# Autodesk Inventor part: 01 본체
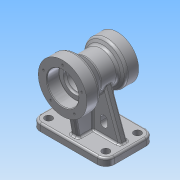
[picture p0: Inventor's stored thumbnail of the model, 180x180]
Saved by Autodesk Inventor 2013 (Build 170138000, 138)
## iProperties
Created: 2015-08
Part Number: 01 본체
Material: 알루미늄 6061
Document SubType Name: Modeling
Designer: Administrator
Density: 2.71 g/cm^3
Mass: 1062.79 g
Surface Area: 749.652 cm^2
Volume: 392.172 cm^3
Author: Administrator
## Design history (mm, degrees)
sketch "스케치1"
  geometry: L1 (-61, 40)-(61, 40); L2 (61, 40)-(61, -40); L3 (61, -40)-(-61, -40); L4 (-61, -40)-(-61, 40); L5 (-61, 40)-(61, -40); 2 further points
  constraints: 10 end point, 2 parallel, 1 coincident, 1 horizontal, 1 midpoint, 1 perpendicular
  dimensions: "d0" = 122 distance of L1.start L1.end; "d3" = 80 distance of L1.end L2.end
extrude "돌출1" new body sketch "스케치1" distance "d4" = 12; taper "d5" = 0 deg
sketch "스케치2"
  geometry: L1 (-40, 0)-(40, 0) reference; L2 (40, 0)-(40, 12) reference; L3 (-40, 12)-(40, 12) reference; L4 (-40, 0)-(-40, 12) reference; L5 (40, 0)-(40, 125); L6 (40, 125)-(20, 125); L7 (20, 125)-(14.804, 116); L8 (14.804, 116)-(-13.315, 116); L9 (-13.315, 116)-(-30, 130); L10 (-30, 130)-(-50, 130); L11 (-50, 130)-(-50, 90); L12 (-50, 90)-(40, 90); 1 further point
  constraints: 16 end point, 4 parallel, 2 perpendicular, 1 point on line
  dimensions: "d8" = 60 deg angle of L8 L7; "d9" = 40 deg angle of L8 L9; "d10" = 70 diameter of L6 L12; "d12" = 80 diameter of L10 L12; "d13" = 180 diameter of L1 L12; "d14" = 52 diameter of L8 L12; "d15" = 90 distance of L11.end L12.end; "d16" = 20 distance of L9.end L10.end; "d17" = 20 distance of L5.end L6.end
revolve "회전1" sketch "스케치2" stored, may be unused: angle "d18" = 90 deg
sketch "스케치3"
  geometry: L1 (61, 0)-(-61, 0) reference; L2 (-61, 0)-(-61, 12) reference; L3 (61, 12)-(-61, 12) reference; L4 (61, 0)-(61, 12) reference; L5 (25.091, 83.185)-(51, 12); L6 (25.091, 83.185)-(-25.091, 83.185); L7 (-25.091, 83.185)-(-51, 12); L8 (0, 0)-(0, 83.185); A1 r 26 centre (0, 90) between (25.091, 83.185) and (-25.091, 83.185) reference
  constraints: 8 end point, 2 point on circle, 2 point on line, 1 midpoint, 1 perpendicular, 1 other
  dimensions: "d19" = 70 deg angle of L3 L5; "d20" = 10 distance from line of L4 L5.end
extrude "돌출2" join sketch "스케치3" stored distance "d21" = 12; taper "d22" = 0 deg
extrude "돌출3" join sketch "스케치4" stored distance "d28" = 12; taper "d29" = 0 deg
sketch "스케치5"
  geometry: L1 (-47, 26)-(47, 26); L2 (47, 26)-(47, -26); L3 (47, -26)-(-47, -26); L4 (-47, -26)-(-47, 26); L5 (-47, 26)-(47, -26); 6 further points
  constraints: 10 end point, 5 coincident, 2 parallel, 1 horizontal, 1 midpoint, 1 perpendicular
  dimensions: "d30" = 94 distance of L1.start L1.end; "d32" = 52 distance of L1.end L2.end
hole "구멍1" sketch "스케치5" at (-47, 26), (-47, -26), (47, -26), (47, 26) diameter "d33" = 12; stored, may be unused: countersink angle "d37" = 90 deg, drill point angle "d39" = 118 deg; dims "d34" = 6, "d35" = 4, "d36" = 2, "d38" = 8
fillet "모깎기1" dims "d40" = 14
sketch "스케치6" dims "d41" = 66
  geometry: L1 (0, 0)-(0, 33); C1 r 40 at (0, 0) reference; 2 further points
  constraints: 2 coincident, 2 end point, 1 vertical, 1 vertical alignment, 2 other
hole "구멍2" sketch "스케치6" at (0, 33) diameter "d42" = 3.242; stored, may be unused: countersink angle "d46" = 90 deg, drill point angle "d48" = 118 deg; dims "d43" = 10, "d44" = 4, "d45" = 2, "d47" = 13
sketch "스케치7" dims "d52" = 54
  geometry: L1 (0, 0)-(0, -27); C1 r 35 at (0, 0) reference; 2 further points
  constraints: 2 coincident, 2 end point, 1 vertical, 1 vertical alignment, 2 other
hole "구멍3" sketch "스케치7" at (0, -27) diameter "d53" = 3.242; stored, may be unused: countersink angle "d57" = 90 deg, drill point angle "d59" = 118 deg; dims "d54" = 10, "d55" = 4, "d56" = 2, "d58" = 13
sketch "스케치8"
  geometry: C1 r 40 at (0, 0) reference; C2 r 26 at (0, 0); 1 further point
  constraints: 1 centre point, 1 coincident
  dimensions: "d63" = 52 diameter of C2
extrude "돌출4" cut sketch "스케치8" distance "d64" = 20; taper "d65" = 0 deg
sketch "스케치9"
  geometry: C1 r 26 at (0, 0) reference; C2 r 19 at (0, 0); 1 further point
  constraints: 1 centre point, 1 coincident
  dimensions: "d66" = 38 diameter of C2
extrude "돌출5" cut sketch "스케치9" distance "d67" = 3; taper "d68" = 0 deg
sketch "스케치10"
  geometry: C1 r 19 at (0, 0) reference; C2 r 16 at (0, 0); 1 further point
  constraints: 1 centre point, 1 coincident
  dimensions: "d69" = 32 diameter of C2
extrude "돌출6" cut sketch "스케치10" stored distance "d70" = 3; taper "d71" = 0 deg
sketch "스케치11"
  geometry: C1 r 16 at (0, 0) reference; C2 r 35 at (0, 0) reference; C3 r 20 at (0, 0); 1 further point
  constraints: 1 centre point, 1 coincident
  dimensions: "d72" = 40 diameter of C3
extrude "돌출7" cut sketch "스케치11" distance "d73" = 17; taper "d74" = 0 deg
chamfer "모따기1" distance "d75" = 1; stored, may be unused: second distance "d76" = 2, angle "d77" = 45 deg
sketch "스케치12"
  geometry: L1 (51, 12)-(6, 12) reference; L2 (18, 36)-(18, 30); L3 (30, 36)-(30, 30); L4 (0, 0)-(0, 90); L5 (-47, 0)-(47, 0) reference; A1 r 26 centre (0, 90) between (6, 64.702) and (25.091, 83.185) reference; A2 r 6 centre (24, 36) between (18, 36) and (30, 36); A3 r 6 centre (24, 30) between (18, 30) and (30, 30)
  constraints: 6 end point, 4 point on circle, 2 centre point, 2 tangent, 1 parallel, 1 perpendicular, 1 vertical alignment
  dimensions: "d78" = 12 diameter of A2; "d79" = 12 diameter of A3; "d80" = 24 distance from line of L4 A3.centre; "d81" = 30 distance from line of L5 A3.centre; "d82" = 6 distance of A2.centre A3.centre
extrude "돌출8" cut sketch "스케치12" distance "d83" = 12; taper "d84" = 0 deg
fillet "모깎기2" dims "d85" = 0.3
fillet "모깎기4" dims "d87" = 3
fillet "모깎기5" dims "d88" = 3
fillet "모깎기7" dims "d90" = 3
fillet "모깎기8" dims "d91" = 5
fillet "모깎기9" dims "d92" = 3
sketch "스케치13"
  geometry: L1 (12, 40)-(12, 26) reference; L2 (52.119, 30)-(15, 30) reference; 2 further points
  constraints: 1 other
  dimensions: "d93" = 24 distance from line of L1 point (36, 14); "d94" = 16 distance from line of point (36, 14) L2
feature "엠보싱1" sketch "스케치13" dims "d0" = 122, "d3" = 80, "d16" = 20, "d95" = 0.5, "d96" = 0
fillet "모깎기10" dims "d97" = 3
fillet "모깎기11" dims "d98" = 3
node "솔리드1"
pattern_circular "원형 패턴1" dims angle "d50" = 360 deg
pattern_circular "원형 패턴2" dims angle "d61" = 360 deg
mirror "대칭1"
node "투영된 루프1"
node "투영된 루프2"
other parameters: "d24" = 71.14874, "d27" = 80 deg
